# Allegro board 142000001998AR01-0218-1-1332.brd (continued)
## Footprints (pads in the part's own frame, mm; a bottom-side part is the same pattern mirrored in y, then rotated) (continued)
CAP_6D1_2SP_4D3W7D3L2D8H_AC
  rect 2.413x2.921 smd: A(3.05,0) C(-3.05,0)
CAP_6D4_2SP_4D3W7D3L2D1H
  rect 2.413x2.794 smd: A(3.2,0) C(-3.2,0)
CAP_6D4_2SP_4D3W7D3L4D3H
  rect 2.413x2.794 smd: A(3.2,0) C(-3.2,0)
CC0402
  rect 0.559x0.539 smd: 1(0,0.454) 2(0,-0.454)
CC0402_22X22_8OCT
  custom 0.14x0.14 smd: 1(0,0.5) 2(0,-0.5)
CC0603
  rect 0.813x0.813 smd: 1(0,0.762) 2(0,-0.762)
CC0805
  rect 1.27x1.016 smd: 1(0,1.016) 2(0,-1.016)
CC1206
  rect 1.524x1.524 smd: 1(0,1.397) 2(0,-1.397)
CC1210
  rect 2.54x1.27 smd: 1(0,1.6) 2(0,-1.6)
CHOKE_3D7_2SP_4W4D5L2H
  rect 1.524x2.54 smd: 1(-1.85,0) 2(1.85,0)
CHOKE_6D05_2SP_6D6WL5H
  rect 2.413x3.556 smd: 1(-3.025,0) 2(3.025,0)
CONN_1D_8SP_10W4D25L
  rect 0.61x1.575 smd: 1(-3.5,0) 2(-2.5,0) 3(-1.5,0) 4(-0.5,0) 5(0.5,0) 6(1.5,0) 7(2.5,0) 8(3.5,0)
  rect 1.219x1.803 smd: G1(-4.8,-3.875) G2(4.8,-3.875)
CONN_2D54_3SP_4W7D62L9D3H_1
  rect 1.016x3.302 smd: 1(-2.54,1.25) 2(0,-1.25) 3(2.54,1.25)
CONN_2D54X5D61_2X5SP_12D7W5L
  rect 1.27x2.794 smd: 1(5.08,2.805) 2(5.08,-2.805) 3(2.54,2.805) 4(2.54,-2.805) 5(0,2.805) 6(0,-2.805) 7(-2.54,2.805) 8(-2.54,-2.805) 9(-5.08,2.805) 10(-5.08,-2.805)
CONN_D5X7D55_75SP_21D9W4D2H
  round 1.118 hole 1.118 unplated: (-10,0)
  round 1.6 hole 1.6 unplated: (10,0)
  rect 0.305x1.524 smd: 1(-9.25,5.275) 2(-9,-2.275) 3(-8.75,5.275) 4(-8.5,-2.275) 5(-8.25,5.275) 6(-8,-2.275) 7(-7.75,5.275) 8(-7.5,-2.275) 9(-7.25,5.275) 10(-7,-2.275) 11(-6.75,5.275) 20(-4.5,-2.275) 21(-4.25,5.275) 22(-4,-2.275) 23(-3.75,5.275) 24(-3.5,-2.275) 25(-3.25,5.275) 26(-3,-2.275) 27(-2.75,5.275) 28(-2.5,-2.275) 29(-2.25,5.275) 30(-2,-2.275) 31(-1.75,5.275) 32(-1.5,-2.275) 33(-1.25,5.275) 34(-1,-2.275) 35(-0.75,5.275) 36(-0.5,-2.275) 37(-0.25,5.275) 38(0,-2.275) 39(0.25,5.275) 40(0.5,-2.275) 41(0.75,5.275) 42(1,-2.275) 43(1.25,5.275) 44(1.5,-2.275) 45(1.75,5.275) 46(2,-2.275) 47(2.25,5.275) 48(2.5,-2.275) 49(2.75,5.275) 50(3,-2.275) 51(3.25,5.275) 52(3.5,-2.275) 53(3.75,5.275) 54(4,-2.275) 55(4.25,5.275) 56(4.5,-2.275) 57(4.75,5.275) 58(5,-2.275) 59(5.25,5.275) 60(5.5,-2.275) 61(5.75,5.275) 62(6,-2.275) 63(6.25,5.275) 64(6.5,-2.275) 65(6.75,5.275) 66(7,-2.275) 67(7.25,5.275) 68(7.5,-2.275) 69(7.75,5.275) 70(8,-2.275) 71(8.25,5.275) 72(8.5,-2.275) 73(8.75,5.275) 74(9,-2.275) 75(9.25,5.275)
  rect 1.27x2.794 smd: G1(-10.35,4.5) G2(10.35,4.5)
CONN_D5X8D2_260SP_73W24D5L
  round 1.118 hole 1.118 unplated: (-34.4,0)
  round 1.6 hole 1.6 unplated: (34.4,0)
  rect 0.305x1.778 smd: 1(33.375,4.1) 2(33.125,-4.1) 3(32.875,4.1) 4(32.625,-4.1) 5(32.375,4.1) 6(32.125,-4.1) 7(31.875,4.1) 8(31.625,-4.1) 9(31.375,4.1) 10(31.125,-4.1) 11(30.875,4.1) 12(30.625,-4.1) 13(30.375,4.1) 14(30.125,-4.1) 15(29.875,4.1) 16(29.625,-4.1) 17(29.375,4.1) 18(29.125,-4.1) 19(28.875,4.1) 20(28.625,-4.1) 21(28.375,4.1) 22(28.125,-4.1) 23(27.875,4.1) 24(27.625,-4.1) 25(27.375,4.1) 26(27.125,-4.1) 27(26.875,4.1) 28(26.625,-4.1) 29(26.375,4.1) 30(26.125,-4.1) 31(25.875,4.1) 32(25.625,-4.1) 33(25.375,4.1) 34(25.125,-4.1) 35(24.875,4.1) 36(24.625,-4.1) 37(24.375,4.1) 38(24.125,-4.1) 39(23.875,4.1) 40(23.625,-4.1) 41(23.375,4.1) 42(23.125,-4.1) 43(22.875,4.1) 44(22.625,-4.1) 45(22.375,4.1) 46(22.125,-4.1) 47(21.875,4.1) 48(21.625,-4.1) 49(21.375,4.1) 50(21.125,-4.1) 51(20.875,4.1) 52(20.625,-4.1) 53(20.375,4.1) 54(20.125,-4.1) 55(19.875,4.1) 56(19.625,-4.1) 57(19.375,4.1) 58(19.125,-4.1) 59(18.875,4.1) 60(18.625,-4.1) 61(18.375,4.1) 62(18.125,-4.1) 63(17.875,4.1) 64(17.625,-4.1) 65(17.375,4.1) 66(17.125,-4.1) 67(16.875,4.1) 68(16.625,-4.1) 69(16.375,4.1) 70(16.125,-4.1) 71(15.875,4.1) 72(15.625,-4.1) 73(15.375,4.1) 74(15.125,-4.1) 75(14.875,4.1) 76(14.625,-4.1) 77(14.375,4.1) 78(14.125,-4.1) 79(13.875,4.1) 80(13.625,-4.1) 81(13.375,4.1) 82(13.125,-4.1) 83(12.875,4.1) 84(12.625,-4.1) 85(12.375,4.1) 86(12.125,-4.1) 87(11.875,4.1) 88(11.625,-4.1) 89(11.375,4.1) 90(11.125,-4.1) 91(10.875,4.1) 92(10.625,-4.1) 93(10.375,4.1) 94(10.125,-4.1) 95(9.875,4.1) 96(9.625,-4.1) 97(9.375,4.1) 98(9.125,-4.1) 99(8.875,4.1) 100(8.625,-4.1) 101(8.375,4.1) 102(8.125,-4.1) 103(7.875,4.1) 104(7.625,-4.1) 105(7.375,4.1) 106(7.125,-4.1) 107(6.875,4.1) 108(6.625,-4.1) 109(6.375,4.1) 110(6.125,-4.1) 111(5.875,4.1) 112(5.625,-4.1) 113(5.375,4.1) 114(5.125,-4.1) 115(4.875,4.1) 116(4.625,-4.1) 117(4.375,4.1) 118(4.125,-4.1) 119(3.875,4.1) 120(3.625,-4.1) 121(3.375,4.1) 122(3.125,-4.1) 123(2.875,4.1) 124(2.625,-4.1) 125(2.375,4.1) 126(2.125,-4.1) 127(1.875,4.1) 128(1.625,-4.1) 129(1.375,4.1) 130(1.125,-4.1) 131(0.875,4.1) 132(0.625,-4.1) 133(0.375,4.1) 134(0.125,-4.1) 135(-0.125,4.1) 136(-0.375,-4.1) 137(-0.625,4.1) 138(-0.875,-4.1) 139(-1.125,4.1) 140(-1.375,-4.1) 141(-1.625,4.1) 142(-1.875,-4.1) 143(-2.125,4.1) 144(-2.375,-4.1) 145(-4.625,4.1) 146(-4.875,-4.1) 147(-5.125,4.1) 148(-5.375,-4.1) 149(-5.625,4.1) 150(-5.875,-4.1) 151(-6.125,4.1) 152(-6.375,-4.1) 153(-6.625,4.1) 154(-6.875,-4.1) 155(-7.125,4.1) 156(-7.375,-4.1) 157(-7.625,4.1) 158(-7.875,-4.1) 159(-8.125,4.1) 160(-8.375,-4.1) 161(-8.625,4.1) 162(-8.875,-4.1) 163(-9.125,4.1) 164(-9.375,-4.1) 165(-9.625,4.1) 166(-9.875,-4.1) 167(-10.125,4.1) 168(-10.375,-4.1) 169(-10.625,4.1) 170(-10.875,-4.1) 171(-11.125,4.1) 172(-11.375,-4.1) 173(-11.625,4.1) 174(-11.875,-4.1) 175(-12.125,4.1) 176(-12.375,-4.1) 177(-12.625,4.1) 178(-12.875,-4.1) 179(-13.125,4.1) 180(-13.375,-4.1) 181(-13.625,4.1) 182(-13.875,-4.1) 183(-14.125,4.1) 184(-14.375,-4.1) 185(-14.625,4.1) 186(-14.875,-4.1) 187(-15.125,4.1) 188(-15.375,-4.1) 189(-15.625,4.1) 190(-15.875,-4.1) 191(-16.125,4.1) 192(-16.375,-4.1) 193(-16.625,4.1) 194(-16.875,-4.1) 195(-17.125,4.1) 196(-17.375,-4.1) 197(-17.625,4.1) 198(-17.875,-4.1) 199(-18.125,4.1) 200(-18.375,-4.1) 201(-18.625,4.1) 202(-18.875,-4.1) 203(-19.125,4.1) 204(-19.375,-4.1) 205(-19.625,4.1) 206(-19.875,-4.1) 207(-20.125,4.1) 208(-20.375,-4.1) 209(-20.625,4.1) 210(-20.875,-4.1) 211(-21.125,4.1) 212(-21.375,-4.1) 213(-21.625,4.1) 214(-21.875,-4.1) 215(-22.125,4.1) 216(-22.375,-4.1) 217(-22.625,4.1) 218(-22.875,-4.1) 219(-23.125,4.1) 220(-23.375,-4.1) 221(-23.625,4.1) 222(-23.875,-4.1) 223(-24.125,4.1) 224(-24.375,-4.1) 225(-24.625,4.1) 226(-24.875,-4.1) 227(-25.125,4.1) 228(-25.375,-4.1) 229(-25.625,4.1) 230(-25.875,-4.1) 231(-26.125,4.1) 232(-26.375,-4.1) 233(-26.625,4.1) 234(-26.875,-4.1) 235(-27.125,4.1) 236(-27.375,-4.1) 237(-27.625,4.1) 238(-27.875,-4.1) 239(-28.125,4.1) 240(-28.375,-4.1) 241(-28.625,4.1) 242(-28.875,-4.1) 243(-29.125,4.1) 244(-29.375,-4.1) 245(-29.625,4.1) 246(-29.875,-4.1) 247(-30.125,4.1) 248(-30.375,-4.1) 249(-30.625,4.1) 250(-30.875,-4.1) 251(-31.125,4.1) 252(-31.375,-4.1) 253(-31.625,4.1) 254(-31.875,-4.1) 255(-32.125,4.1) 256(-32.375,-4.1) 257(-32.625,4.1) 258(-32.875,-4.1) 259(-33.125,4.1) 260(-33.375,-4.1)
  rect 3.556x4.572 smd: G1(33.8,12) G2(-33.8,12)
CONN_D5X8D2_260SP_73W24D5L_1
  round 1.118 hole 1.118 unplated: (-34.4,0)
  round 1.6 hole 1.6 unplated: (34.4,0)
  rect 0.305x1.778 smd: 1(33.375,4.1) 2(33.125,-4.1) 3(32.875,4.1) 4(32.625,-4.1) 5(32.375,4.1) 6(32.125,-4.1) 7(31.875,4.1) 8(31.625,-4.1) 9(31.375,4.1) 10(31.125,-4.1) 11(30.875,4.1) 12(30.625,-4.1) 13(30.375,4.1) 14(30.125,-4.1) 15(29.875,4.1) 16(29.625,-4.1) 17(29.375,4.1) 18(29.125,-4.1) 19(28.875,4.1) 20(28.625,-4.1) 21(28.375,4.1) 22(28.125,-4.1) 23(27.875,4.1) 24(27.625,-4.1) 25(27.375,4.1) 26(27.125,-4.1) 27(26.875,4.1) 28(26.625,-4.1) 29(26.375,4.1) 30(26.125,-4.1) 31(25.875,4.1) 32(25.625,-4.1) 33(25.375,4.1) 34(25.125,-4.1) 35(24.875,4.1) 36(24.625,-4.1) 37(24.375,4.1) 38(24.125,-4.1) 39(23.875,4.1) 40(23.625,-4.1) 41(23.375,4.1) 42(23.125,-4.1) 43(22.875,4.1) 44(22.625,-4.1) 45(22.375,4.1) 46(22.125,-4.1) 47(21.875,4.1) 48(21.625,-4.1) 49(21.375,4.1) 50(21.125,-4.1) 51(20.875,4.1) 52(20.625,-4.1) 53(20.375,4.1) 54(20.125,-4.1) 55(19.875,4.1) 56(19.625,-4.1) 57(19.375,4.1) 58(19.125,-4.1) 59(18.875,4.1) 60(18.625,-4.1) 61(18.375,4.1) 62(18.125,-4.1) 63(17.875,4.1) 64(17.625,-4.1) 65(17.375,4.1) 66(17.125,-4.1) 67(16.875,4.1) 68(16.625,-4.1) 69(16.375,4.1) 70(16.125,-4.1) 71(15.875,4.1) 72(15.625,-4.1) 73(15.375,4.1) 74(15.125,-4.1) 75(14.875,4.1) 76(14.625,-4.1) 77(14.375,4.1) 78(14.125,-4.1) 79(13.875,4.1) 80(13.625,-4.1) 81(13.375,4.1) 82(13.125,-4.1) 83(12.875,4.1) 84(12.625,-4.1) 85(12.375,4.1) 86(12.125,-4.1) 87(11.875,4.1) 88(11.625,-4.1) 89(11.375,4.1) 90(11.125,-4.1) 91(10.875,4.1) 92(10.625,-4.1) 93(10.375,4.1) 94(10.125,-4.1) 95(9.875,4.1) 96(9.625,-4.1) 97(9.375,4.1) 98(9.125,-4.1) 99(8.875,4.1) 100(8.625,-4.1) 101(8.375,4.1) 102(8.125,-4.1) 103(7.875,4.1) 104(7.625,-4.1) 105(7.375,4.1) 106(7.125,-4.1) 107(6.875,4.1) 108(6.625,-4.1) 109(6.375,4.1) 110(6.125,-4.1) 111(5.875,4.1) 112(5.625,-4.1) 113(5.375,4.1) 114(5.125,-4.1) 115(4.875,4.1) 116(4.625,-4.1) 117(4.375,4.1) 118(4.125,-4.1) 119(3.875,4.1) 120(3.625,-4.1) 121(3.375,4.1) 122(3.125,-4.1) 123(2.875,4.1) 124(2.625,-4.1) 125(2.375,4.1) 126(2.125,-4.1) 127(1.875,4.1) 128(1.625,-4.1) 129(1.375,4.1) 130(1.125,-4.1) 131(0.875,4.1) 132(0.625,-4.1) 133(0.375,4.1) 134(0.125,-4.1) 135(-0.125,4.1) 136(-0.375,-4.1) 137(-0.625,4.1) 138(-0.875,-4.1) 139(-1.125,4.1) 140(-1.375,-4.1) 141(-1.625,4.1) 142(-1.875,-4.1) 143(-2.125,4.1) 144(-2.375,-4.1) 145(-4.625,4.1) 146(-4.875,-4.1) 147(-5.125,4.1) 148(-5.375,-4.1) 149(-5.625,4.1) 150(-5.875,-4.1) 151(-6.125,4.1) 152(-6.375,-4.1) 153(-6.625,4.1) 154(-6.875,-4.1) 155(-7.125,4.1) 156(-7.375,-4.1) 157(-7.625,4.1) 158(-7.875,-4.1) 159(-8.125,4.1) 160(-8.375,-4.1) 161(-8.625,4.1) 162(-8.875,-4.1) 163(-9.125,4.1) 164(-9.375,-4.1) 165(-9.625,4.1) 166(-9.875,-4.1) 167(-10.125,4.1) 168(-10.375,-4.1) 169(-10.625,4.1) 170(-10.875,-4.1) 171(-11.125,4.1) 172(-11.375,-4.1) 173(-11.625,4.1) 174(-11.875,-4.1) 175(-12.125,4.1) 176(-12.375,-4.1) 177(-12.625,4.1) 178(-12.875,-4.1) 179(-13.125,4.1) 180(-13.375,-4.1) 181(-13.625,4.1) 182(-13.875,-4.1) 183(-14.125,4.1) 184(-14.375,-4.1) 185(-14.625,4.1) 186(-14.875,-4.1) 187(-15.125,4.1) 188(-15.375,-4.1) 189(-15.625,4.1) 190(-15.875,-4.1) 191(-16.125,4.1) 192(-16.375,-4.1) 193(-16.625,4.1) 194(-16.875,-4.1) 195(-17.125,4.1) 196(-17.375,-4.1) 197(-17.625,4.1) 198(-17.875,-4.1) 199(-18.125,4.1) 200(-18.375,-4.1) 201(-18.625,4.1) 202(-18.875,-4.1) 203(-19.125,4.1) 204(-19.375,-4.1) 205(-19.625,4.1) 206(-19.875,-4.1) 207(-20.125,4.1) 208(-20.375,-4.1) 209(-20.625,4.1) 210(-20.875,-4.1) 211(-21.125,4.1) 212(-21.375,-4.1) 213(-21.625,4.1) 214(-21.875,-4.1) 215(-22.125,4.1) 216(-22.375,-4.1) 217(-22.625,4.1) 218(-22.875,-4.1) 219(-23.125,4.1) 220(-23.375,-4.1) 221(-23.625,4.1) 222(-23.875,-4.1) 223(-24.125,4.1) 224(-24.375,-4.1) 225(-24.625,4.1) 226(-24.875,-4.1) 227(-25.125,4.1) 228(-25.375,-4.1) 229(-25.625,4.1) 230(-25.875,-4.1) 231(-26.125,4.1) 232(-26.375,-4.1) 233(-26.625,4.1) 234(-26.875,-4.1) 235(-27.125,4.1) 236(-27.375,-4.1) 237(-27.625,4.1) 238(-27.875,-4.1) 239(-28.125,4.1) 240(-28.375,-4.1) 241(-28.625,4.1) 242(-28.875,-4.1) 243(-29.125,4.1) 244(-29.375,-4.1) 245(-29.625,4.1) 246(-29.875,-4.1) 247(-30.125,4.1) 248(-30.375,-4.1) 249(-30.625,4.1) 250(-30.875,-4.1) 251(-31.125,4.1) 252(-31.375,-4.1) 253(-31.625,4.1) 254(-31.875,-4.1) 255(-32.125,4.1) 256(-32.375,-4.1) 257(-32.625,4.1) 258(-32.875,-4.1) 259(-33.125,4.1) 260(-33.375,-4.1)
  rect 2.032x3.556 smd: G1(-37.75,12) G2(37.75,8)
CONNF_D5X5D728_2X30SP_21D3W
  round 1.016 hole 1.016 unplated: (-2.813,5.53) (17.313,5.53)
  rect 0.254x2.286 smd: 1(0,0) 2(0,5.728) 3(0.5,0) 4(0.5,5.728) 5(1,0) 6(1,5.728) 7(1.5,0) 8(1.5,5.728) 9(2,0) 10(2,5.728) 11(2.5,0) 12(2.5,5.728) 13(3,0) 14(3,5.728) 15(3.5,0) 16(3.5,5.728) 17(4,0) 18(4,5.728) 19(4.5,0) 20(4.5,5.728) 21(5,0) 22(5,5.728) 23(5.5,0) 24(5.5,5.728) 25(6,0) 26(6,5.728) 27(6.5,0) 28(6.5,5.728) 29(7,0) 30(7,5.728) 31(7.5,0) 32(7.5,5.728) 33(8,0) 34(8,5.728) 35(8.5,0) 36(8.5,5.728) 37(9,0) 38(9,5.728) 39(9.5,0) 40(9.5,5.728) 41(10,0) 42(10,5.728) 43(10.5,0) 44(10.5,5.728) 45(11,0) 46(11,5.728) 47(11.5,0) 48(11.5,5.728) 49(12,0) 50(12,5.728) 51(12.5,0) 52(12.5,5.728) 53(13,0) 54(13,5.728) 55(13.5,0) 56(13.5,5.728) 57(14,0) 58(14,5.728) 59(14.5,0) 60(14.5,5.728)
CONNF_D8_2X26SP_29D9W8D2L5D6H
  round 1.6 hole 1.6 unplated: (-12.5,0)
  round 1.092 hole 1.092 unplated: (12.5,0)
  rect 0.559x2.032 smd: 1(-11.8,-4.1) 2(-11.4,4.1) 3(-11,-4.1) 4(-10.6,4.1) 5(-10.2,-4.1) 6(-9.8,4.1) 7(-9.4,-4.1) 8(-9,4.1) 9(-8.6,-4.1) 10(-8.2,4.1) 11(-7.8,-4.1) 12(-7.4,4.1) 13(-7,-4.1) 14(-6.6,4.1) 15(-6.2,-4.1) 16(-5.8,4.1) 17(-2.2,-4.1) 18(-1.8,4.1) 19(-1.4,-4.1) 20(-1,4.1) 21(-0.6,-4.1) 22(-0.2,4.1) 23(0.2,-4.1) 24(0.6,4.1) 25(1,-4.1) 26(1.4,4.1) 27(1.8,-4.1) 28(2.2,4.1) 29(2.6,-4.1) 30(3,4.1) 31(3.4,-4.1) 32(3.8,4.1) 33(4.2,-4.1) 34(4.6,4.1) 35(5,-4.1) 36(5.4,4.1) 37(5.8,-4.1) 38(6.2,4.1) 39(6.6,-4.1) 40(7,4.1) 41(7.4,-4.1) 42(7.8,4.1) 43(8.2,-4.1) 44(8.6,4.1) 45(9,-4.1) 46(9.4,4.1) 47(9.8,-4.1) 48(10.2,4.1) 49(10.6,-4.1) 50(11,4.1) 51(11.4,-4.1) 52(11.8,4.1)
  rect 2.286x3.175 smd: G1(-14.65,-3.5) G2(14.65,-3.5)
CONNM_1D27X4D1_2X4SP_3D8H
  rect 0.762x2.54 smd: 1(1.905,-2.05) 2(1.905,2.05) 3(0.635,-2.05) 4(0.635,2.05) 5(-0.635,-2.05) 6(-0.635,2.05) 7(-1.905,-2.05) 8(-1.905,2.05)
CONNM_2D54X2D5_2X2SP_10D16W9D8H
  rect 1.016x3.302 smd: 1(3.81,-1.25) 2(1.27,1.25) 3(-1.27,-1.25) 4(-3.81,1.25)
CONNM_D5X5D32_2X60SP_COMBO_2
  round 1.499 hole 1.499 unplated: (-18.535,0) (18.535,0)
  round 1.219 hole 1.219 unplated: (-16.756,-3.016) (16.724,-3.016)
  rect 0.305x2.413 smd: 1(14.743,-3.591) 3(14.243,-3.591) 5(13.743,-3.591) 7(13.243,-3.591) 9(12.743,-3.591) 11(12.243,-3.591) 13(11.743,-3.591) 15(11.243,-3.591) 17(10.743,-3.591) 19(10.243,-3.591) 21(9.743,-3.591) 23(9.243,-3.591) 25(8.743,-3.591) 27(8.243,-3.591) 29(7.743,-3.591) 31(7.243,-3.591) 33(6.743,-3.591) 35(6.243,-3.591) 37(5.743,-3.591) 39(5.243,-3.591) 41(4.743,-3.591) 43(4.243,-3.591) 45(3.743,-3.591) 47(3.243,-3.591) 49(2.743,-3.591) 51(2.243,-3.591) 53(1.743,-3.591) 55(1.243,-3.591) 57(0.743,-3.591) 59(0.243,-3.591) 61(-0.257,-3.591) 63(-0.757,-3.591) 65(-1.257,-3.591) 67(-1.757,-3.591) 69(-2.257,-3.591) 71(-2.757,-3.591) 73(-3.257,-3.591) 75(-3.757,-3.591) 77(-4.257,-3.591) 79(-4.757,-3.591) 81(-5.257,-3.591) 83(-5.757,-3.591) 85(-6.257,-3.591) 87(-6.757,-3.591) 89(-7.257,-3.591) 91(-7.757,-3.591) 93(-8.257,-3.591) 95(-8.757,-3.591) 97(-9.257,-3.591) 99(-9.757,-3.591) 101(-10.257,-3.591) 103(-10.757,-3.591) 105(-11.257,-3.591) 107(-11.757,-3.591) 109(-12.257,-3.591) 111(-12.757,-3.591) 113(-13.257,-3.591) 115(-13.757,-3.591) 117(-14.257,-3.591) 119(-14.757,-3.591)
  rect 0.305x2.388 smd: 2(14.743,1.828) 4(14.243,1.828) 6(13.743,1.828) 8(13.243,1.828) 10(12.743,1.828) 12(12.243,1.828) 14(11.743,1.828) 16(11.243,1.828) 18(10.743,1.828) 20(10.243,1.828) 22(9.743,1.828) 24(9.243,1.828) 26(8.743,1.828) 28(8.243,1.828) 30(7.743,1.828) 32(7.243,1.828) 34(6.743,1.828) 36(6.243,1.828) 38(5.743,1.828) 40(5.243,1.828) 42(4.743,1.828) 44(4.243,1.828) 46(3.743,1.828) 48(3.243,1.828) 50(2.743,1.828) 52(2.243,1.828) 54(1.743,1.828) 56(1.243,1.828) 58(0.743,1.828) 60(0.243,1.828) 62(-0.257,1.828) 64(-0.757,1.828) 66(-1.257,1.828) 68(-1.757,1.828) 70(-2.257,1.828) 72(-2.757,1.828) 74(-3.257,1.828) 76(-3.757,1.828) 78(-4.257,1.828) 80(-4.757,1.828) 82(-5.257,1.828) 84(-5.757,1.828) 86(-6.257,1.828) 88(-6.757,1.828) 90(-7.257,1.828) 92(-7.757,1.828) 94(-8.257,1.828) 96(-8.757,1.828) 98(-9.257,1.828) 100(-9.757,1.828) 102(-10.257,1.828) 104(-10.757,1.828) 106(-11.257,1.828) 108(-11.757,1.828) 110(-12.257,1.828) 112(-12.757,1.828) 114(-13.257,1.828) 116(-13.757,1.828) 118(-14.257,1.828) 120(-14.757,1.828)
  round 1.524 hole 1.092: G1(16.945,2.54) G2(-16.945,2.54) G3(-19.172,-3.048) G4(19.168,-3.048)
DFN_D5X3D_10SP_3WL1H_G1
  rect 0.254x0.813 smd: 1(-1,-1.5) 2(-0.5,-1.5) 3(0,-1.5) 4(0.5,-1.5) 5(1,-1.5) 6(1,1.5) 7(0.5,1.5) 8(0,1.5) 9(-0.5,1.5) 10(-1,1.5)
  rect 2.54x1.651 smd: G1(0,0)
DIOSCHTKY_2SP_1D6WX2D7L_AC
  rect 1.016x1.016 smd: A(0,-1.778) C(0,1.778)
FBGA_1D_20C_256SP_17WL
  round 0.508 smd: (-9.5,-9.5) (9.5,9.5) A1(-7.5,7.5) A2(-6.5,7.5) A3(-5.5,7.5) A4(-4.5,7.5) A5(-3.5,7.5) A6(-2.5,7.5) A7(-1.5,7.5) A8(-0.5,7.5) A9(0.5,7.5) A10(1.5,7.5) A11(2.5,7.5) A12(3.5,7.5) A13(4.5,7.5) A14(5.5,7.5) A15(6.5,7.5) A16(7.5,7.5) B1(-7.5,6.5) B2(-6.5,6.5) B3(-5.5,6.5) B4(-4.5,6.5) B5(-3.5,6.5) B6(-2.5,6.5) B7(-1.5,6.5) B8(-0.5,6.5) B9(0.5,6.5) B10(1.5,6.5) B11(2.5,6.5) B12(3.5,6.5) B13(4.5,6.5) B14(5.5,6.5) B15(6.5,6.5) B16(7.5,6.5) C1(-7.5,5.5) C2(-6.5,5.5) C3(-5.5,5.5) C4(-4.5,5.5) C5(-3.5,5.5) C6(-2.5,5.5) C7(-1.5,5.5) C8(-0.5,5.5) C9(0.5,5.5) C10(1.5,5.5) C11(2.5,5.5) C12(3.5,5.5) C13(4.5,5.5) C14(5.5,5.5) C15(6.5,5.5) C16(7.5,5.5) D1(-7.5,4.5) D2(-6.5,4.5) D3(-5.5,4.5) D4(-4.5,4.5) D5(-3.5,4.5) D6(-2.5,4.5) D7(-1.5,4.5) D8(-0.5,4.5) D9(0.5,4.5) D10(1.5,4.5) D11(2.5,4.5) D12(3.5,4.5) D13(4.5,4.5) D14(5.5,4.5) D15(6.5,4.5) D16(7.5,4.5) E1(-7.5,3.5) E2(-6.5,3.5) E3(-5.5,3.5) E4(-4.5,3.5) E5(-3.5,3.5) E6(-2.5,3.5) E7(-1.5,3.5) E8(-0.5,3.5) E9(0.5,3.5) E10(1.5,3.5) E11(2.5,3.5) E12(3.5,3.5) E13(4.5,3.5) E14(5.5,3.5) E15(6.5,3.5) E16(7.5,3.5) F1(-7.5,2.5) F2(-6.5,2.5) F3(-5.5,2.5) F4(-4.5,2.5) F5(-3.5,2.5) F6(-2.5,2.5) F7(-1.5,2.5) F8(-0.5,2.5) F9(0.5,2.5) F10(1.5,2.5) F11(2.5,2.5) F12(3.5,2.5) F13(4.5,2.5) F14(5.5,2.5) F15(6.5,2.5) F16(7.5,2.5) G1(-7.5,1.5) G2(-6.5,1.5) G3(-5.5,1.5) G4(-4.5,1.5) G5(-3.5,1.5) G6(-2.5,1.5) G7(-1.5,1.5) G8(-0.5,1.5) G9(0.5,1.5) G10(1.5,1.5) G11(2.5,1.5) G12(3.5,1.5) G13(4.5,1.5) G14(5.5,1.5) G15(6.5,1.5) G16(7.5,1.5) H1(-7.5,0.5) H2(-6.5,0.5) H3(-5.5,0.5) H4(-4.5,0.5) H5(-3.5,0.5) H6(-2.5,0.5) H7(-1.5,0.5) H8(-0.5,0.5) H9(0.5,0.5) H10(1.5,0.5) H11(2.5,0.5) H12(3.5,0.5) H13(4.5,0.5) H14(5.5,0.5) H15(6.5,0.5) H16(7.5,0.5) J1(-7.5,-0.5) J2(-6.5,-0.5) J3(-5.5,-0.5) J4(-4.5,-0.5) J5(-3.5,-0.5) J6(-2.5,-0.5) J7(-1.5,-0.5) J8(-0.5,-0.5) J9(0.5,-0.5) J10(1.5,-0.5) J11(2.5,-0.5) J12(3.5,-0.5) J13(4.5,-0.5) J14(5.5,-0.5) J15(6.5,-0.5) J16(7.5,-0.5) K1(-7.5,-1.5) K2(-6.5,-1.5) K3(-5.5,-1.5) K4(-4.5,-1.5) K5(-3.5,-1.5) K6(-2.5,-1.5) K7(-1.5,-1.5) K8(-0.5,-1.5) K9(0.5,-1.5) K10(1.5,-1.5) K11(2.5,-1.5) K12(3.5,-1.5) K13(4.5,-1.5) K14(5.5,-1.5) K15(6.5,-1.5) K16(7.5,-1.5) L1(-7.5,-2.5) L2(-6.5,-2.5) L3(-5.5,-2.5) L4(-4.5,-2.5) L5(-3.5,-2.5) L6(-2.5,-2.5) L7(-1.5,-2.5) L8(-0.5,-2.5) L9(0.5,-2.5) L10(1.5,-2.5) L11(2.5,-2.5) L12(3.5,-2.5) L13(4.5,-2.5) L14(5.5,-2.5) L15(6.5,-2.5) L16(7.5,-2.5) M1(-7.5,-3.5) M2(-6.5,-3.5) M3(-5.5,-3.5) M4(-4.5,-3.5) M5(-3.5,-3.5) M6(-2.5,-3.5) M7(-1.5,-3.5) M8(-0.5,-3.5) M9(0.5,-3.5) M10(1.5,-3.5) M11(2.5,-3.5) M12(3.5,-3.5) M13(4.5,-3.5) M14(5.5,-3.5) M15(6.5,-3.5) M16(7.5,-3.5) N1(-7.5,-4.5) N2(-6.5,-4.5) N3(-5.5,-4.5) N4(-4.5,-4.5) N5(-3.5,-4.5) N6(-2.5,-4.5) N7(-1.5,-4.5) N8(-0.5,-4.5) N9(0.5,-4.5) N10(1.5,-4.5) N11(2.5,-4.5) N12(3.5,-4.5) N13(4.5,-4.5) N14(5.5,-4.5) N15(6.5,-4.5) N16(7.5,-4.5) P1(-7.5,-5.5) P2(-6.5,-5.5) P3(-5.5,-5.5) P4(-4.5,-5.5) P5(-3.5,-5.5) P6(-2.5,-5.5) P7(-1.5,-5.5) P8(-0.5,-5.5) P9(0.5,-5.5) P10(1.5,-5.5) P11(2.5,-5.5) P12(3.5,-5.5) P13(4.5,-5.5) P14(5.5,-5.5) P15(6.5,-5.5) P16(7.5,-5.5) R1(-7.5,-6.5) R2(-6.5,-6.5) R3(-5.5,-6.5) R4(-4.5,-6.5) R5(-3.5,-6.5) R6(-2.5,-6.5) R7(-1.5,-6.5) R8(-0.5,-6.5) R9(0.5,-6.5) R10(1.5,-6.5) R11(2.5,-6.5) R12(3.5,-6.5) R13(4.5,-6.5) R14(5.5,-6.5) R15(6.5,-6.5) R16(7.5,-6.5) T1(-7.5,-7.5) T2(-6.5,-7.5) T3(-5.5,-7.5) T4(-4.5,-7.5) T5(-3.5,-7.5) T6(-2.5,-7.5) T7(-1.5,-7.5) T8(-0.5,-7.5) T9(0.5,-7.5) T10(1.5,-7.5) T11(2.5,-7.5) T12(3.5,-7.5) T13(4.5,-7.5) T14(5.5,-7.5) T15(6.5,-7.5) T16(7.5,-7.5)
HSINK_60D_4DP_70WL13D3H
  round 4.496 hole 4.496 unplated: (-30,30) (-30,-30) (30,30) (30,-30)
  round 0.559 hole 0.305: 1(-30.14,33.151) 2(29.86,33.151) 3(-30.14,-26.849) 4(29.86,-26.849)
HSINK_60D_4DPNP_71W70L_1
  round 4.496 hole 4.496 unplated: (-30,-30) (-30,30) (30,-30) (30,30)
IND_5D1_2SP_7D1WL4D2H
  rect 2.794x2.286 smd: 1(-2.55,0) 2(2.55,0)
IND_7D7_2SP_7D8W10D2L
  rect 2.54x3.048 smd: 1(0,3.85) 2(0,-3.85)
LC0603
  rect 0.813x0.813 smd: 1(0,0.762) 2(0,-0.762)
LC0805
  rect 1.524x1.27 smd: 1(0,1.016) 2(0,-1.016)
LC1206
  rect 1.905x1.524 smd: 1(0,1.524) 2(0,-1.524)
LED_1D5_2SP_D8W1D6LD6H_AC
  rect 0.813x0.813 smd: A(0,0.75) C(0,-0.75)
LED_1D65XD85_4SP_1D25W1D6L_AC
  rect 0.813x0.406 smd: A1(-0.825,0.425) A2(-0.825,-0.425) C1(0.825,0.425) C2(0.825,-0.425)
M_CONN_2D54X5D35_2X5SP
  round 1.803 hole 1.803 unplated: (0,3.81) (0,-3.81)
  custom 0.318x0.318 smd: 1(-2.472,-5.08) 2(2.472,-5.08) 3(-2.472,-2.54) 4(2.472,-2.54) 7(-2.472,2.54) 8(2.472,2.54) 9(-2.472,5.08)
  rect 3.454x1.27 smd: 5(-2.472,0) 6(2.472,0)
MTH_276C138D_8DP
  round 0 hole 3.505 unplated: (0,0)
  custom 0.407x0.407 hole 0.305: 1(0,2.629) 3(2.629,0) 5(0,-2.629) 7(-2.629,0)
  custom 0.407x0.407 hole 0.305 rot 135: 2(1.859,1.859) 6(-1.859,-1.859)
  custom 0.407x0.407 hole 0.305 rot 45: 4(1.859,-1.859) 8(-1.859,1.859)
NUT_236C134D_3D2H
  round 5.994 hole 3.404: 1(0,0)
NUT_335C166D
  round 4.216 hole 4.216 unplated: (0,0)
  round 0.178 smd: 1(0.054,2.677)
OSC_1D6X2D12_4SP_2D5W3D2L1DH
  rect 1.422x1.219 smd: 1(-1.06,-0.8) 2(1.06,-0.8) 3(1.06,0.8) 4(-1.06,0.8)
OSC_1D6X2D12_4SP_2D5W3D2LD75H
  rect 1.524x1.194 smd: 1(-1.06,-0.8) 2(1.06,-0.8) 3(1.06,0.8) 4(-1.06,0.8)
OSC_1D7X2D2_4SP_2D5W3D2L1D1H
  rect 1.422x1.219 smd: 1(-1.1,-0.85) 2(1.1,-0.85) 3(1.1,0.85) 4(-1.1,0.85)
QFN_D4X5D_40SP_5WLD85H
  rect 0.813x0.203 smd: 1(-2.5,1.8) 2(-2.5,1.4) 3(-2.5,1) 4(-2.5,0.6) 5(-2.5,0.2) 6(-2.5,-0.2) 7(-2.5,-0.6) 8(-2.5,-1) 9(-2.5,-1.4) 10(-2.5,-1.8) 21(2.5,-1.8) 22(2.5,-1.4) 23(2.5,-1) 24(2.5,-0.6) 25(2.5,-0.2) 26(2.5,0.2) 27(2.5,0.6) 28(2.5,1) 29(2.5,1.4) 30(2.5,1.8)
  rect 0.203x0.813 smd: 11(-1.8,-2.5) 12(-1.4,-2.5) 13(-1,-2.5) 14(-0.6,-2.5) 15(-0.2,-2.5) 16(0.2,-2.5) 17(0.6,-2.5) 18(1,-2.5) 19(1.4,-2.5) 20(1.8,-2.5) 31(1.8,2.5) 32(1.4,2.5) 33(1,2.5) 34(0.6,2.5) 35(0.2,2.5) 36(-0.2,2.5) 37(-0.6,2.5) 38(-1,2.5) 39(-1.4,2.5) 40(-1.8,2.5)
  rect 3.683x3.683 smd: G1(0,0)
QFN_D5_25SP_4W6L_IOR
  rect 0.65x0.249 smd: 1(-2,2.3) 2(-2,1.8) 3(-2,1.3) 4(-2,0.8) 5(-2,0.3) 6(-2,-2.349)
  rect 0.249x0.599 smd: 7(-1,-3) 8(-0.5,-3) 9(0,-3) 10(0.5,-3) 11(1,-3) 17(1.374,3.025) 23(-1.575,3.025)
  rect 0.65x0.399 smd: 12(2,-1.575) 13(2,-0.535) 14(2,0.6) 15(2,1.83)
  rect 0.559x0.254 smd: 16(2.001,2.45)
  rect 0.249x0.65 smd: 18(0.925,3) 19(0.425,3) 20(-0.075,3) 21(-0.575,3) 22(-1.075,3)
  rect 1.631x1.951 smd: 24(-0.485,1.351)
  rect 0.551x0.34 smd: 25(-0.98,-0.505)
QFN_D5_32SP_6WL_IOR
  rect 0.599x0.249 smd: 1(-2.92,2.278)
  rect 0.65x0.249 smd: 2(-2.894,1.778) 3(-2.894,1.278) 4(-2.894,0.777) 5(-2.894,0.277) 6(-2.894,-2.372)
  rect 0.249x0.599 smd: 7(-1.993,-2.873) 8(-1.492,-2.873) 9(-0.994,-2.873) 10(-0.494,-2.873) 11(0.006,-2.873) 12(0.507,-2.873) 13(1.007,-2.873) 14(1.507,-2.873) 15(2.008,-2.873) 30(-2.569,2.929)
  rect 0.65x0.399 smd: 16(2.856,-1.598) 17(2.856,-0.559) 18(2.856,0.577) 19(2.856,1.808)
  rect 0.249x0.65 smd: 20(2.432,2.903) 21(1.932,2.903) 22(1.431,2.903) 23(0.931,2.903) 24(0.431,2.903) 25(-0.067,2.903) 26(-0.568,2.903) 27(-1.068,2.903) 28(-1.568,2.903) 29(-2.069,2.903)
  rect 1.631x1.951 smd: 31(-1.48,1.328)
  rect 0.551x0.34 smd: 32(-2.049,-0.528)
QFN_D5X2D5X3D5_16SP_3D5W2D5L
  rect 0.813x0.305 smd: 1(-1.75,-0.25) 8(1.75,-0.25) 9(1.75,0.25) 16(-1.75,0.25)
  rect 0.305x0.813 smd: 2(-1.25,-1.25) 3(-0.75,-1.25) 4(-0.25,-1.25) 5(0.25,-1.25) 6(0.75,-1.25) 7(1.25,-1.25) 10(1.25,1.25) 11(0.75,1.25) 12(0.25,1.25) 13(-0.25,1.25) 14(-0.75,1.25) 15(-1.25,1.25)
  rect 2.032x1.016 smd: G1(0,0)
QFN_D5X2D95_11SP_3D15WL
  custom 0.07x0.07 smd: 1(-1,-1.475) 2(-0.5,-1.475) 3(0,-1.475) 4(0.5,-1.475) 5(1,-1.475) 6(1,1.475) 7(0.5,1.475) 8(0,1.475) 9(-0.5,1.475) 10(-1,1.475)
  custom 0.412x0.412 smd: 11(0,0)
QFN_D5X3D5X5D5_24SP_5D5W3D5L
  rect 0.813x0.305 smd: 1(-2.75,-0.75) 12(2.75,-0.75) 13(2.75,0.75) 24(-2.75,0.75)
  rect 0.305x0.813 smd: 2(-2.25,-1.75) 3(-1.75,-1.75) 4(-1.25,-1.75) 5(-0.75,-1.75) 6(-0.25,-1.75) 7(0.25,-1.75) 8(0.75,-1.75) 9(1.25,-1.75) 10(1.75,-1.75) 11(2.25,-1.75) 14(2.25,1.75) 15(1.75,1.75) 16(1.25,1.75) 17(0.75,1.75) 18(0.25,1.75) 19(-0.25,1.75) 20(-0.75,1.75) 21(-1.25,1.75) 22(-1.75,1.75) 23(-2.25,1.75)
  rect 4.064x2.032 smd: G1(0,0)
QFN_D5X9D_64SP_9WL1H_3D4SQ
  rect 0.813x0.254 smd: 1(-4.5,3.75) 2(-4.5,3.25) 3(-4.5,2.75) 4(-4.5,2.25) 5(-4.5,1.75) 6(-4.5,1.25) 7(-4.5,0.75) 8(-4.5,0.25) 9(-4.5,-0.25) 10(-4.5,-0.75) 11(-4.5,-1.25) 12(-4.5,-1.75) 13(-4.5,-2.25) 14(-4.5,-2.75) 15(-4.5,-3.25) 16(-4.5,-3.75) 33(4.5,-3.75) 34(4.5,-3.25) 35(4.5,-2.75) 36(4.5,-2.25) 37(4.5,-1.75) 38(4.5,-1.25) 39(4.5,-0.75) 40(4.5,-0.25) 41(4.5,0.25) 42(4.5,0.75) 43(4.5,1.25) 44(4.5,1.75) 45(4.5,2.25) 46(4.5,2.75) 47(4.5,3.25) 48(4.5,3.75)
  rect 0.254x0.813 smd: 17(-3.75,-4.5) 18(-3.25,-4.5) 19(-2.75,-4.5) 20(-2.25,-4.5) 21(-1.75,-4.5) 22(-1.25,-4.5) 23(-0.75,-4.5) 24(-0.25,-4.5) 25(0.25,-4.5) 26(0.75,-4.5) 27(1.25,-4.5) 28(1.75,-4.5) 29(2.25,-4.5) 30(2.75,-4.5) 31(3.25,-4.5) 32(3.75,-4.5) 49(3.75,4.5) 50(3.25,4.5) 51(2.75,4.5) 52(2.25,4.5) 53(1.75,4.5) 54(1.25,4.5) 55(0.75,4.5) 56(0.25,4.5) 57(-0.25,4.5) 58(-0.75,4.5) 59(-1.25,4.5) 60(-1.75,4.5) 61(-2.25,4.5) 62(-2.75,4.5) 63(-3.25,4.5) 64(-3.75,4.5)
  rect 3.429x3.429 smd: G1(0,0)
QFN_D65X2D_6SP_2WL1H
  rect 0.254x0.457 smd: 1(-0.65,-1) 2(0,-1) 3(0.65,-1) 4(0.65,1) 5(0,1) 6(-0.65,1)
  rect 0.254x0.762 smd: 7(0.735,0.002)
  rect 1.016x1.067 smd: 8(-0.3,0.002)
RC0402
  rect 0.559x0.539 smd: 1(0,0.454) 2(0,-0.454)
RC0603
  rect 0.813x0.813 smd: 1(0,0.762) 2(0,-0.762)
RC0805
  rect 1.27x1.016 smd: 1(0,1.016) 2(0,-1.016)
RC2512
  rect 3.556x1.778 smd: 1(0,3.175) 2(0,-3.175)
SC70_D65X1D9_6SP_1D25W2LD95H
  rect 0.381x0.508 smd: 1(-0.65,-0.95) 2(0,-0.95) 3(0.65,-0.95) 4(0.65,0.95) 5(0,0.95) 6(-0.65,0.95)
SO8_1D27X5D3_8SP_3D9W4D9L
  rect 1.524x0.635 smd: 1(-2.65,1.905) 2(-2.65,0.635) 3(-2.65,-0.635) 4(-2.65,-1.905) 5(2.65,-1.905) 6(2.65,-0.635) 7(2.65,0.635) 8(2.65,1.905)
SOCKET_SODIMM_D6X8D2_204SP_TB
  round 1.6 hole 1.6 unplated: (-33.4,0)
  round 1.143 hole 1.143 unplated: (33.4,0)
  rect 0.356x2.032 smd: 1(-31.65,-4.1) 2(-31.35,4.1) 3(-31.05,-4.1) 4(-30.75,4.1) 5(-30.45,-4.1) 6(-30.15,4.1) 7(-29.85,-4.1) 8(-29.55,4.1) 9(-29.25,-4.1) 10(-28.95,4.1) 11(-28.65,-4.1) 12(-28.35,4.1) 13(-28.05,-4.1) 14(-27.75,4.1) 15(-27.45,-4.1) 16(-27.15,4.1) 17(-26.85,-4.1) 18(-26.55,4.1) 19(-26.25,-4.1) 20(-25.95,4.1) 21(-25.65,-4.1) 22(-25.35,4.1) 23(-25.05,-4.1) 24(-24.75,4.1) 25(-24.45,-4.1) 26(-24.15,4.1) 27(-23.85,-4.1) 28(-23.55,4.1) 29(-23.25,-4.1) 30(-22.95,4.1) 31(-22.65,-4.1) 32(-22.35,4.1) 33(-22.05,-4.1) 34(-21.75,4.1) 35(-21.45,-4.1) 36(-21.15,4.1) 37(-20.85,-4.1) 38(-20.55,4.1) 39(-20.25,-4.1) 40(-19.95,4.1) 41(-19.65,-4.1) 42(-19.35,4.1) 43(-19.05,-4.1) 44(-18.75,4.1) 45(-18.45,-4.1) 46(-18.15,4.1) 47(-17.85,-4.1) 48(-17.55,4.1) 49(-17.25,-4.1) 50(-16.95,4.1) 51(-16.65,-4.1) 52(-16.35,4.1) 53(-16.05,-4.1) 54(-15.75,4.1) 55(-15.45,-4.1) 56(-15.15,4.1) 57(-14.85,-4.1) 58(-14.55,4.1) 59(-14.25,-4.1) 60(-13.95,4.1) 61(-13.65,-4.1) 62(-13.35,4.1) 63(-13.05,-4.1) 64(-12.75,4.1) 65(-12.45,-4.1) 66(-12.15,4.1) 67(-11.85,-4.1) 68(-11.55,4.1) 69(-11.25,-4.1) 70(-10.95,4.1) 71(-10.65,-4.1) 72(-10.35,4.1) 73(-7.65,-4.1) 74(-7.35,4.1) 75(-7.05,-4.1) 76(-6.75,4.1) 77(-6.45,-4.1) 78(-6.15,4.1) 79(-5.85,-4.1) 80(-5.55,4.1) 81(-5.25,-4.1) 82(-4.95,4.1) 83(-4.65,-4.1) 84(-4.35,4.1) 85(-4.05,-4.1) 86(-3.75,4.1) 87(-3.45,-4.1) 88(-3.15,4.1) 89(-2.85,-4.1) 90(-2.55,4.1) 91(-2.25,-4.1) 92(-1.95,4.1) 93(-1.65,-4.1) 94(-1.35,4.1) 95(-1.05,-4.1) 96(-0.75,4.1) 97(-0.45,-4.1) 98(-0.15,4.1) 99(0.15,-4.1) 100(0.45,4.1) 101(0.75,-4.1) 102(1.05,4.1) 103(1.35,-4.1) 104(1.65,4.1) 105(1.95,-4.1) 106(2.25,4.1) 107(2.55,-4.1) 108(2.85,4.1) 109(3.15,-4.1) 110(3.45,4.1) 111(3.75,-4.1) 112(4.05,4.1) 113(4.35,-4.1) 114(4.65,4.1) 115(4.95,-4.1) 116(5.25,4.1) 117(5.55,-4.1) 118(5.85,4.1) 119(6.15,-4.1) 120(6.45,4.1) 121(6.75,-4.1) 122(7.05,4.1) 123(7.35,-4.1) 124(7.65,4.1) 125(7.95,-4.1) 126(8.25,4.1) 127(8.55,-4.1) 128(8.85,4.1) 129(9.15,-4.1) 130(9.45,4.1) 131(9.75,-4.1) 132(10.05,4.1) 133(10.35,-4.1) 134(10.65,4.1) 135(10.95,-4.1) 136(11.25,4.1) 137(11.55,-4.1) 138(11.85,4.1) 139(12.15,-4.1) 140(12.45,4.1) 141(12.75,-4.1) 142(13.05,4.1) 143(13.35,-4.1) 144(13.65,4.1) 145(13.95,-4.1) 146(14.25,4.1) 147(14.55,-4.1) 148(14.85,4.1) 149(15.15,-4.1) 150(15.45,4.1) 151(15.75,-4.1) 152(16.05,4.1) 153(16.35,-4.1) 154(16.65,4.1) 155(16.95,-4.1) 156(17.25,4.1) 157(17.55,-4.1) 158(17.85,4.1) 159(18.15,-4.1) 160(18.45,4.1) 161(18.75,-4.1) 162(19.05,4.1) 163(19.35,-4.1) 164(19.65,4.1) 165(19.95,-4.1) 166(20.25,4.1) 167(20.55,-4.1) 168(20.85,4.1) 169(21.15,-4.1) 170(21.45,4.1) 171(21.75,-4.1) 172(22.05,4.1) 173(22.35,-4.1) 174(22.65,4.1) 175(22.95,-4.1) 176(23.25,4.1) 177(23.55,-4.1) 178(23.85,4.1) 179(24.15,-4.1) 180(24.45,4.1) 181(24.75,-4.1) 182(25.05,4.1) 183(25.35,-4.1) 184(25.65,4.1) 185(25.95,-4.1) 186(26.25,4.1) 187(26.55,-4.1) 188(26.85,4.1) 189(27.15,-4.1) 190(27.45,4.1) 191(27.75,-4.1) 192(28.05,4.1) 193(28.35,-4.1) 194(28.65,4.1) 195(28.95,-4.1) 196(29.25,4.1) 197(29.55,-4.1) 198(29.85,4.1) 199(30.15,-4.1) 200(30.45,4.1) 201(30.75,-4.1) 202(31.05,4.1) 203(31.35,-4.1) 204(31.65,4.1)
  rect 3.556x4.572 smd: G1(-32.8,12) G2(32.8,12)
SOIC_1D27X5D16_8SP_3D9W4D925L
  rect 1.651x0.508 smd: 1(-2.58,1.905) 2(-2.58,0.635) 3(-2.58,-0.635) 4(-2.58,-1.905) 5(2.58,-1.905) 6(2.58,-0.635) 7(2.58,0.635) 8(2.58,1.905)
SOIC_1D27X5D165_8SP_3D9W4D9L
  rect 1.651x0.508 smd: 1(-2.582,1.905) 2(-2.582,0.635) 3(-2.582,-0.635) 4(-2.582,-1.905) 5(2.582,-1.905) 6(2.582,-0.635) 7(2.582,0.635) 8(2.582,1.905)
SOIC_1D27X7D25_8SP_5D23WL2D16H
  rect 1.397x0.508 smd: 1(-3.625,1.905) 2(-3.625,0.635) 3(-3.625,-0.635) 4(-3.625,-1.905) 5(3.625,-1.905) 6(3.625,-0.635) 7(3.625,0.635) 8(3.625,1.905)
SOP_1D27X5D24_8SP_5L
  rect 1.778x0.508 smd: 1(-2.794,1.905) 2(-2.794,0.635) 3(-2.794,-0.635) 4(-2.794,-1.905) 5(2.794,-1.905) 6(2.794,-0.635) 7(2.794,0.635) 8(2.794,1.905)
SOP_D65X4D35_8SP_3WL
  rect 1.27x0.381 smd: 1(-2.175,0.975) 2(-2.175,0.325) 3(-2.175,-0.325) 4(-2.175,-0.975) 5(2.175,-0.975) 6(2.175,-0.325) 7(2.175,0.325) 8(2.175,0.975)
SOT23_1D9X2D2_3SP_1D3W2D92LGSD
  rect 1.016x1.397 smd: D(0,1.1) G(-0.95,-1.1) S(0.95,-1.1)
SOT23_1D9X2D_3SP_1D3W2D95L1D15H
  rect 0.813x0.914 smd: A1(-0.95,-1) A2(0.95,-1) C(0,1)
SOT23_3SP_GSD
  rect 1.016x1.016 smd: D(0,1.016) G(-1.016,-1.016) S(1.016,-1.016)
SOT23_6SP_D95
  rect 0.635x1.27 smd: 1(-0.95,-1.27) 2(0,-1.27) 3(0.95,-1.27) 4(0.95,1.27) 5(0,1.27) 6(-0.95,1.27)
SOT363_D65_6SP_1D25W2L1D1H
  rect 0.381x1.016 smd: 1(-0.65,-0.887) 2(0,-0.887) 3(0.65,-0.887) 4(0.65,0.887) 5(0,0.887) 6(-0.65,0.887)
SSOP_D635X5D355_16SP_3D91W4D9L
  rect 1.397x0.381 smd: 1(-2.677,2.225) 2(-2.677,1.59) 3(-2.677,0.955) 4(-2.677,0.32) 5(-2.677,-0.315) 6(-2.677,-0.95) 7(-2.677,-1.585) 8(-2.677,-2.22) 9(2.677,-2.22) 10(2.677,-1.585) 11(2.677,-0.95) 12(2.677,-0.315) 13(2.677,0.32) 14(2.677,0.955) 15(2.677,1.59) 16(2.677,2.225)
SW_PUSH_3D15X1D85_4SP_3D5W2D8L
  round 0.889 hole 0.889 unplated: (-0.85,0)
  round 0.711 hole 0.711 unplated: (0.85,0)
  rect 0.965x0.66 smd: 1(-0.925,1.575) 2(0.925,1.575) 3(-0.925,-1.575) 4(0.925,-1.575)
TP_30C0D0C
  round 0.762 smd: 1(0,0)
TSSOP_D65X5D8_16SP_5D1L
  rect 1.524x0.381 smd: 1(-2.925,2.275) 2(-2.925,1.625) 3(-2.925,0.975) 4(-2.925,0.325) 5(-2.925,-0.325) 6(-2.925,-0.975) 7(-2.925,-1.625) 8(-2.925,-2.275) 9(2.925,-2.275) 10(2.925,-1.625) 11(2.925,-0.975) 12(2.925,-0.325) 13(2.925,0.325) 14(2.925,0.975) 15(2.925,1.625) 16(2.925,2.275)
TSSOP_D65X5D8_28SP_4D4W9D7L1D2H
  rect 1.549x0.406 smd: 1(-2.9,4.225) 2(-2.9,3.575) 3(-2.9,2.925) 4(-2.9,2.275) 5(-2.9,1.625) 6(-2.9,0.975) 7(-2.9,0.325) 8(-2.9,-0.325) 9(-2.9,-0.975) 10(-2.9,-1.625) 11(-2.9,-2.275) 12(-2.9,-2.925) 13(-2.9,-3.575) 14(-2.9,-4.225) 15(2.9,-4.225) 16(2.9,-3.575) 17(2.9,-2.925) 18(2.9,-2.275) 19(2.9,-1.625) 20(2.9,-0.975) 21(2.9,-0.325) 22(2.9,0.325) 23(2.9,0.975) 24(2.9,1.625) 25(2.9,2.275) 26(2.9,2.925) 27(2.9,3.575) 28(2.9,4.225)
TSSOP_D65X5D775_14SP_4D4W5L_G1
  rect 1.397x0.381 smd: 1(-2.887,1.95) 2(-2.887,1.3) 3(-2.887,0.65) 4(-2.887,0) 5(-2.887,-0.65) 6(-2.887,-1.3) 7(-2.887,-1.95) 8(2.887,-1.95) 9(2.887,-1.3) 10(2.887,-0.65) 11(2.887,0) 12(2.887,0.65) 13(2.887,1.3) 14(2.887,1.95)
  rect 2.464x2.286 smd: G1(0,0)
TSSOP_D65X5D775_16SP_4D4W5L1D2H
  rect 1.524x0.254 smd: 1(-2.887,2.275) 2(-2.887,1.625) 3(-2.887,0.975) 4(-2.887,0.325) 5(-2.887,-0.325) 6(-2.887,-0.975) 7(-2.887,-1.625) 8(-2.887,-2.275) 9(2.887,-2.275) 10(2.887,-1.625) 11(2.887,-0.975) 12(2.887,-0.325) 13(2.887,0.325) 14(2.887,0.975) 15(2.887,1.625) 16(2.887,2.275)
TSSOP_D65X5D775_24SP_4D4W7D8L
  rect 1.524x0.381 smd: 1(-2.887,3.575) 2(-2.887,2.925) 3(-2.887,2.275) 4(-2.887,1.625) 5(-2.887,0.975) 6(-2.887,0.325) 7(-2.887,-0.325) 8(-2.887,-0.975) 9(-2.887,-1.625) 10(-2.887,-2.275) 11(-2.887,-2.925) 12(-2.887,-3.575) 13(2.887,-3.575) 14(2.887,-2.925) 15(2.887,-2.275) 16(2.887,-1.625) 17(2.887,-0.975) 18(2.887,-0.325) 19(2.887,0.325) 20(2.887,0.975) 21(2.887,1.625) 22(2.887,2.275) 23(2.887,2.925) 24(2.887,3.575)
unnamed#2
  round 1.016 smd: (0,0)
USB_D65_5SP_4D96W7D51L2D71H
  rect 0.406x1.346 smd: 1(1.3,-2.17) 2(0.65,-2.17) 3(0,-2.17) 4(-0.65,-2.17) 5(-1.3,-2.17)
  round 1.143 hole 0.711: G1(-2.425,-2.27) G2(2.425,-2.27)
  oval 1.219x1.626 hole 0.711x1.118: G3(-3.625,0.38) G6(3.625,0.38)
  rect 1.041x1.372 smd: G4(-2.175,0.38) G5(2.175,0.38)
XTAL_2D5_2SP_1D5W3D2L0D9H
  rect 1.143x1.778 smd: 1(-1.25,0) 2(1.25,0)

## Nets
AGND_V3P3: C243.2 C626.2 R727.1 R731.1 R748.2 U27.5(GND)
AGND_V3P3A: C129.2 R620.1 R629.2 R1088.1 U15.5(GND)
AGND_V5A: C34.2 R68.2 R99.1 R455.1 U4.5(GND)
AGND_VDDQ: C221.2 C238.2 C254.2 C625.2 R349.2 R363.2 R723.1 R728.2 R742.2 R756.2 R780.1
